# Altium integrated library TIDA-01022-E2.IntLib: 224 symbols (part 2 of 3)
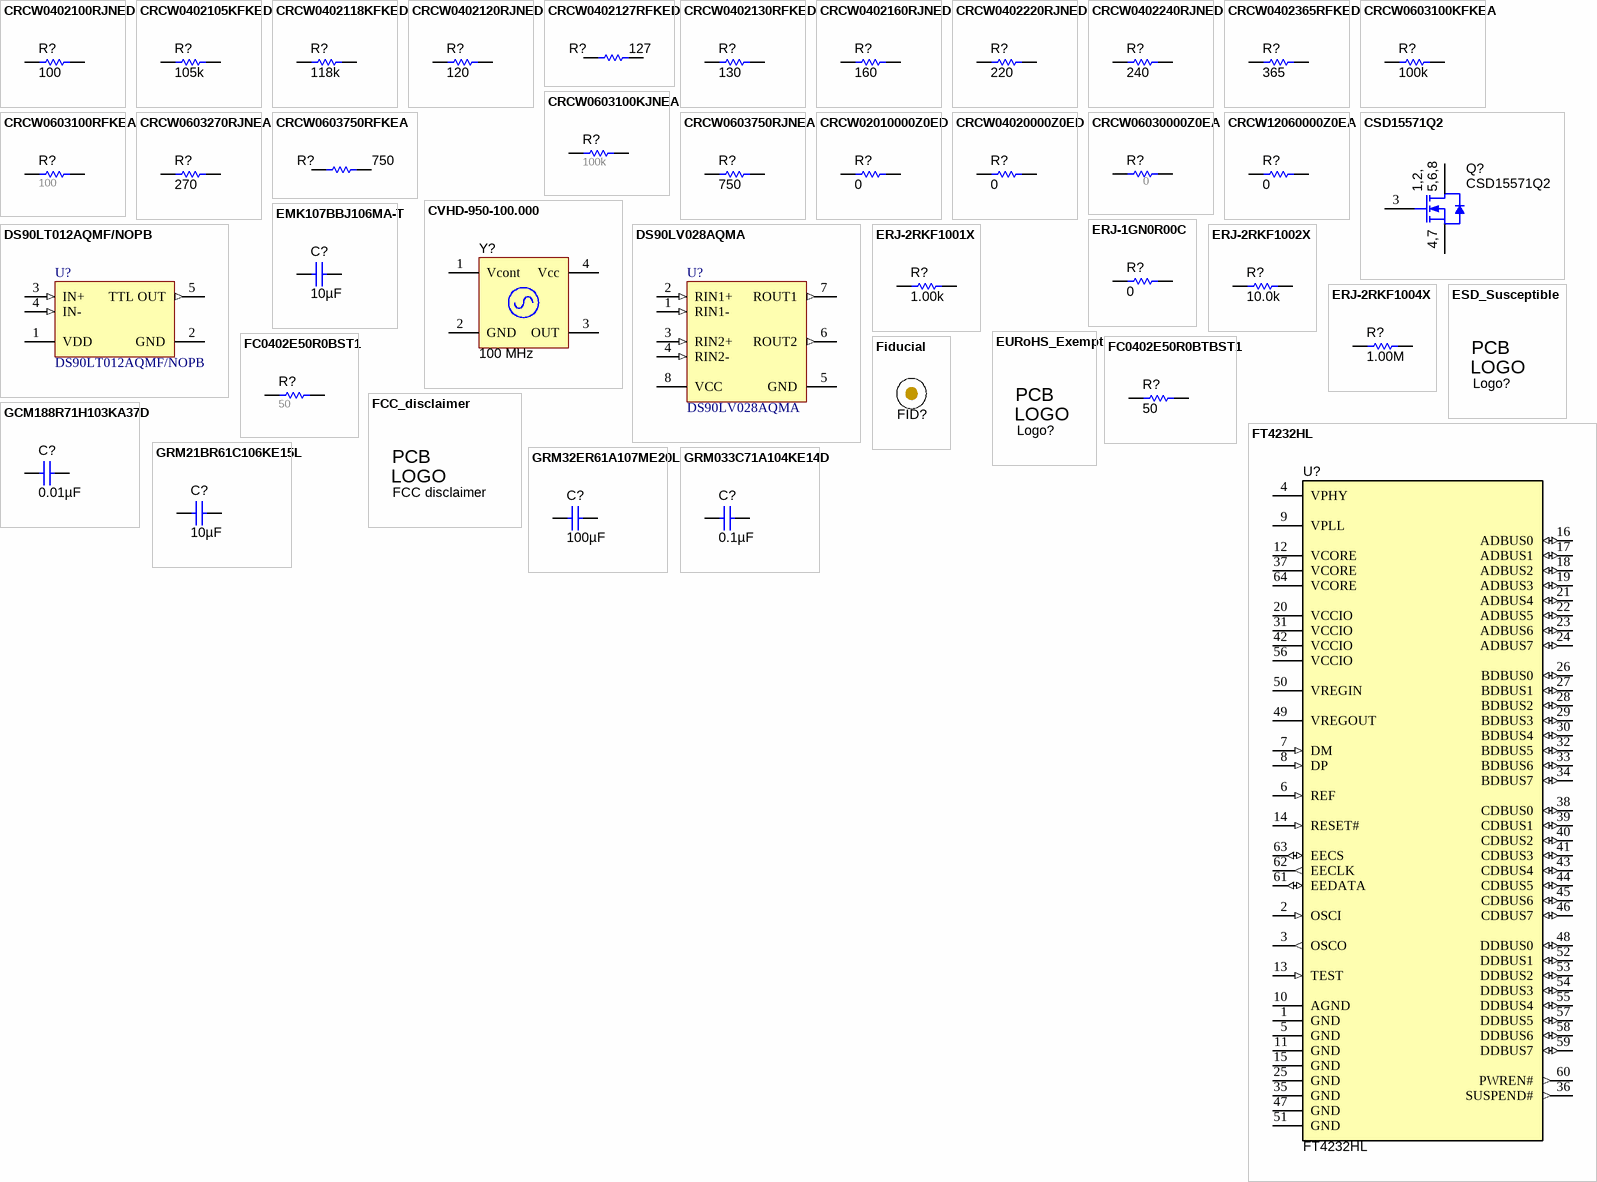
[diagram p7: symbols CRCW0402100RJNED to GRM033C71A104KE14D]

## CRCW0402105KFKED
designator R?  ValueDisplayed: 105k  (hidden comment: CRCW0402105KFKED)
RES, 105 k, 1%, 0.063 W, 0402; Manufacturer: Vishay-Dale; CompType: Resistor; Value: 105k; Res_ohm: 105000; Tolerance_%: 1; Power_W: 0.063; Value2: 0.063W; VDC_V: 50; TempCo: 100 ppm/C; SizeArea_mm2: 0.5; SizeZ_mm: 0.6; EIA_Code: E96; U/M: EA; AEC Category: Q200
signal-integrity model Resistor
simulation model Resistor
footprint 0402
footprint 0402M
footprint 0402L
footprint 0402S
pins: 1, 2

## CRCW0402118KFKED
designator R?  ValueDisplayed: 118k  (hidden comment: CRCW0402118KFKED)
RES, 118 k, 1%, 0.063 W, 0402; Manufacturer: Vishay-Dale; CompType: Resistor; Value: 118k; Res_ohm: 118000; Tolerance_%: 1; Power_W: 0.063; Value2: 0.063W; VDC_V: 50; TempCo: 100 ppm/C; SizeArea_mm2: 0.5; SizeZ_mm: 0.6; EIA_Code: E96; U/M: EA; AEC Category: Q200
signal-integrity model Resistor
simulation model Resistor
footprint 0402
footprint 0402M
footprint 0402L
footprint 0402S
pins: 1, 2

## CRCW0402120RJNED
designator R?  ValueDisplayed: 120  (hidden comment: CRCW0402120RJNED)
RES, 120, 5%, 0.063 W, 0402; Manufacturer: Vishay-Dale; CompType: Resistor; Value: 120; Value_Code: 120R; Tolerance_%: 5; Power_W: 0.063; Value2: 0.063W; VDC_V: 50; TempCo: 200 ppm/C; SizeArea_mm2: 0.5; SizeX_mm: 1; SizeZ_mm: 0.6; EIA_Code: E24; U/M: EA; AEC Category: Q200
signal-integrity model Resistor
simulation model Resistor
footprint 0402
footprint 0402M
footprint 0402L
footprint 0402S
pins: 1, 2

## CRCW0402127RFKED
designator R?  ValueDisplayed: 127  (hidden comment: CRCW0402127RFKED)
RES, 127, 1%, 0.063 W, 0402; Manufacturer: Vishay-Dale; CompType: Resistor; Value: 127; Value_Code: 127R; Tolerance_%: 1; Power_W: 0.063; Value2: 0.063W; VDC_V: 50; TempCo: 100 ppm/C; SizeArea_mm2: 0.5; SizeZ_mm: 0.6; EIA_Code: E96; U/M: EA; AEC Category: Q200
signal-integrity model Resistor
simulation model Resistor
footprint 0402
footprint 0402M
footprint 0402L
footprint 0402S
pins: 1, 2

## CRCW0402130RFKED
designator R?  ValueDisplayed: 130  (hidden comment: CRCW0402130RFKED)
RES, 130, 1%, 0.063 W, 0402; Manufacturer: Vishay-Dale; CompType: Resistor; Value: 130; Value_Code: 130R; Tolerance_%: 1; Power_W: 0.063; Value2: 0.063W; VDC_V: 50; TempCo: 100 ppm/C; SizeArea_mm2: 0.5; SizeZ_mm: 0.6; EIA_Code: E96; U/M: EA; AEC Category: Q200
signal-integrity model Resistor
simulation model Resistor
footprint 0402
footprint 0402M
footprint 0402L
footprint 0402S
pins: 1, 2

## CRCW0402160RJNED
designator R?  ValueDisplayed: 160  (hidden comment: CRCW0402160RJNED)
RES, 160, 5%, 0.063 W, 0402; Manufacturer: Vishay-Dale; CompType: Resistor; Value: 160; Value_Code: 160R; Tolerance_%: 5; Power_W: 0.063; Value2: 0.063W; VDC_V: 50; TempCo: 200 ppm/C; SizeArea_mm2: 0.5; SizeX_mm: 1; SizeZ_mm: 0.6; EIA_Code: E24; U/M: EA; AEC Category: Q200
signal-integrity model Resistor
simulation model Resistor
footprint 0402
footprint 0402M
footprint 0402L
footprint 0402S
pins: 1, 2

## CRCW0402220RJNED
designator R?  ValueDisplayed: 220  (hidden comment: CRCW0402220RJNED)
RES, 220, 5%, 0.063 W, 0402; Manufacturer: Vishay-Dale; CompType: Resistor; Value: 220; Value_Code: 220R; Tolerance_%: 5; Power_W: 0.063; Value2: 0.063W; VDC_V: 50; TempCo: 200 ppm/C; SizeArea_mm2: 0.5; SizeX_mm: 1; SizeZ_mm: 0.6; EIA_Code: E24; U/M: EA; AEC Category: Q200
signal-integrity model Resistor
simulation model Resistor
footprint 0402
footprint 0402M
footprint 0402L
footprint 0402S
pins: 1, 2

## CRCW0402240RJNED
designator R?  ValueDisplayed: 240  (hidden comment: CRCW0402240RJNED)
RES, 240, 5%, 0.063 W, 0402; Manufacturer: Vishay-Dale; CompType: Resistor; Value: 240; Value_Code: 240R; Tolerance_%: 5; Power_W: 0.063; Value2: 0.063W; VDC_V: 50; TempCo: 200 ppm/C; SizeArea_mm2: 0.5; SizeX_mm: 1; SizeZ_mm: 0.6; EIA_Code: E24; U/M: EA; AEC Category: Q200
signal-integrity model Resistor
simulation model Resistor
footprint 0402
footprint 0402M
footprint 0402L
footprint 0402S
pins: 1, 2

## CRCW0402365RFKED
designator R?  ValueDisplayed: 365  (hidden comment: CRCW0402365RFKED)
RES, 365, 1%, 0.063 W, 0402; Manufacturer: Vishay-Dale; CompType: Resistor; Value: 365; Value_Code: 365R; Tolerance_%: 1; Power_W: 0.063; Value2: 0.063W; VDC_V: 50; TempCo: 100 ppm/C; SizeArea_mm2: 0.5; SizeZ_mm: 0.6; EIA_Code: E96; U/M: EA; AEC Category: Q200
signal-integrity model Resistor
simulation model Resistor
footprint 0402
footprint 0402M
footprint 0402L
footprint 0402S
pins: 1, 2

## CRCW0603100KFKEA
designator R?  ValueDisplayed: 100k  (hidden comment: CRCW0603100KFKEA)
RES, 100 k, 1%, 0.1 W, 0603; Manufacturer: Vishay-Dale; CompType: Resistor; Value: 100k; Res_ohm: 100000; Tolerance_%: 1; Power_W: 0.1; Value2: 0.1W; VDC_V: 75; TempCo: 100 ppm/C; SizeArea_mm2: 1.28; SizeX_mm: 1.6; SizeY_mm: 0.8; EIA_Code: E96; U/M: EA; AEC Category: Q200
signal-integrity model Resistor
simulation model Resistor
footprint 0603
footprint 0603M
footprint 0603L
footprint 0603_HV
footprint 0603S
pins: 1, 2

## CRCW0603100KJNEA
designator R?  ValueDisplayed: 100k  (hidden comment: CRCW0603100KJNEA)
RES, 100 k, 5%, 0.1 W, 0603; Manufacturer: Vishay-Dale; CompType: Resistor; Tolerance_%: 5; VDC_V: 75; Power_W: 0.1; Res_ohm: 100000; Value: 100k; U/M: EA; Value2: 0.1W; EIA_Code: E24; TempCo: 200 ppm/C; SizeArea_mm2: 1.28; SizeX_mm: 1.6; SizeY_mm: 0.8; SizeZ_mm: 1; AEC Category: Q200
signal-integrity model Resistor
simulation model Resistor
footprint 0603
footprint 0603M
footprint 0603L
footprint 0603_HV
footprint 0603S
pins: 1, 2

## CRCW0603100RFKEA
designator R?  ValueDisplayed: 100  (hidden comment: CRCW0603100RFKEA)
RES, 100, 1%, 0.1 W, 0603; Manufacturer: Vishay-Dale; CompType: Resistor; Tolerance_%: 1; VDC_V: 75; Power_W: 0.1; Value: 100; U/M: EA; Value_Code: 100R; Value2: 0.1W; EIA_Code: E96; TempCo: 100 ppm/C; SizeArea_mm2: 1.28; SizeX_mm: 1.6; SizeY_mm: 0.8; AEC Category: Q200
signal-integrity model Resistor
simulation model Resistor
footprint 0603
footprint 0603M
footprint 0603L
footprint 0603_HV
footprint 0603S
pins: 1, 2

## CRCW0603270RJNEA
designator R?  ValueDisplayed: 270  (hidden comment: CRCW0603270RJNEA)
RES, 270, 5%, 0.1 W, 0603; Manufacturer: Vishay-Dale; CompType: Resistor; Value: 270; Value_Code: 270R; Tolerance_%: 5; Power_W: 0.1; Value2: 0.1W; VDC_V: 75; TempCo: 200 ppm/C; SizeArea_mm2: 1.28; SizeX_mm: 1.6; SizeY_mm: 0.8; SizeZ_mm: 1; EIA_Code: E24; U/M: EA; AEC Category: Q200
signal-integrity model Resistor
simulation model Resistor
footprint 0603
footprint 0603M
footprint 0603L
footprint 0603_HV
footprint 0603S
pins: 1, 2

## CRCW0603750RFKEA
designator R?  ValueDisplayed: 750  (hidden comment: CRCW0603750RFKEA)
RES, 750, 1%, 0.1 W, 0603; Manufacturer: Vishay-Dale; CompType: Resistor; Value: 750; Value_Code: 750R; Tolerance_%: 1; Power_W: 0.1; Value2: 0.1W; VDC_V: 75; TempCo: 100 ppm/C; SizeArea_mm2: 1.28; SizeX_mm: 1.6; SizeY_mm: 0.8; EIA_Code: E96; U/M: EA; AEC Category: Q200
signal-integrity model Resistor
simulation model Resistor
footprint 0603
footprint 0603M
footprint 0603L
footprint 0603_HV
footprint 0603S
pins: 1, 2

## CRCW0603750RJNEA
designator R?  ValueDisplayed: 750  (hidden comment: CRCW0603750RJNEA)
RES, 750, 5%, 0.1 W, 0603; Manufacturer: Vishay-Dale; CompType: Resistor; Value: 750; Value_Code: 750R; Tolerance_%: 5; Power_W: 0.1; Value2: 0.1W; VDC_V: 75; TempCo: 200 ppm/C; SizeArea_mm2: 1.28; SizeX_mm: 1.6; SizeY_mm: 0.8; SizeZ_mm: 1; EIA_Code: E24; U/M: EA; AEC Category: Q200
signal-integrity model Resistor
simulation model Resistor
footprint 0603
footprint 0603M
footprint 0603L
footprint 0603_HV
footprint 0603S
pins: 1, 2

## CRCW02010000Z0ED
designator R?  ValueDisplayed: 0  (hidden comment: CRCW02010000Z0ED)
RES, 0, 5%, 0.05 W, 0201; Manufacturer: Vishay-Dale; CompType: Resistor; Value: 0; Value_Code: 0000; Tolerance_%: 5; Power_W: 0.05; Value2: 0.05W; TempCo: ppm/C; SizeArea_mm2: 0.18; SizeX_mm: 0.6; SizeY_mm: 0.3; SizeZ_mm: 0.26; EIA_Code: E24; U/M: EA; AEC Category: Q200; AEC Qualified: N
signal-integrity model Resistor
simulation model Resistor
footprint 0201_adc (Data from Kemet datasheet CC101_COM dated 7/28/11)
footprint 0201M
footprint 0201L
footprint 0201_Silk
pins: 1, 2

## CRCW04020000Z0ED
designator R?  ValueDisplayed: 0  (hidden comment: CRCW04020000Z0ED)
RES, 0, 5%, 0.063 W, 0402; Manufacturer: Vishay-Dale; CompType: Resistor; Value: 0; Value_Code: 0000; Tolerance_%: 5; Power_W: 0.063; Value2: 0.063W; VDC_V: 50; TempCo: 200 ppm/C; SizeArea_mm2: 0.5; SizeX_mm: 1; SizeZ_mm: 0.6; EIA_Code: E24; U/M: EA; AEC Category: Q200
signal-integrity model Resistor
simulation model Resistor
footprint 0402
footprint 0402M
footprint 0402L
footprint 0402S
pins: 1, 2

## CRCW06030000Z0EA
designator R?  ValueDisplayed: 0  (hidden comment: CRCW06030000Z0EA)
RES, 0, 5%, 0.1 W, 0603; Manufacturer: Vishay-Dale; CompType: Resistor; Tolerance_%: 5; VDC_V: 75; Power_W: 0.1; Value: 0; U/M: EA; Value_Code: 0000; Value2: 0.1W; EIA_Code: E24; TempCo: 200 ppm/C; SizeArea_mm2: 1.28; SizeX_mm: 1.6; SizeY_mm: 0.8; SizeZ_mm: 1; AEC Category: Q200
signal-integrity model Resistor
simulation model Resistor
footprint 0603
footprint 0603M
footprint 0603L
footprint 0603_HV
footprint 0603S
pins: 1, 2

## CRCW12060000Z0EA
designator R?  ValueDisplayed: 0  (hidden comment: CRCW12060000Z0EA)
RES, 0, 5%, 0.25 W, 1206; Manufacturer: Vishay-Dale; CompType: Resistor; Value: 0; Value_Code: 0000; Tolerance_%: 5; Power_W: 0.25; Value2: 0.25W; VDC_V: 200; TempCo: 200 ppm/C; SizeArea_mm2: 5.12; SizeX_mm: 3.2; SizeY_mm: 1.6; SizeZ_mm: 1.35; EIA_Code: E24; U/M: EA; AEC Category: Q200
signal-integrity model Resistor
simulation model Resistor
footprint 1206
footprint 1206M
footprint 1206L
pins: 1, 2

## CSD15571Q2
designator Q?
MOSFET, N-CH, 20 V, 10 A, DQK0006C (WSON-6); Manufacturer: Texas Instruments; Alternate Manufacturer: None; U/M: EA; ChType: N; Value: 20V; VdsMax_V: 20; Value1: 19.2 ohm; Rdson45_ohm: 19.2; Value2: 2.5 nC; QgTyp_nC: 2.5; IdsMax_A: 10; SizeAreaWB_mm2: 9; SizeArea_mm2: 4; SizeX_mm: 2; SizeZ_mm: 0.8; AEC Category: Q101
footprint DQK0006C
pins: 1 D, 2 D, 3 G, 4 S, 5 D, 6 D, 7 S, 8 D

## CVHD-950-100.000
designator Y?  Frequency: 100 MHz  (hidden comment: CVHD-950-100.000)
VCXO, 100 MHz, 3.3V, SMD; Manufacturer: Crystek Corporation; SymbolCreator: a0412235; CompType: Oscillator; U/M: EA; TaMin_C: 0; TaMax_C: 70; Frequency Stability: ±20ppm
footprint OSC_CVHD-950-4
footprint OSC_CVHD-950-4_ExtPads
pins: 1 Vcont, 2 GND (power), 3 OUT, 4 Vcc (power)

## DS90LT012AQMF/NOPB
designator U?
Automotive LVDS Differential Line Receiver, 5-pin SOT-23, Pb-Free; Manufacturer: Texas Instruments; PackageTopMarking: N03Q*XTT; PowerWise: N; CompType: Interface IC
footprint MF05A_N (SOT23, 5-Leads, Body 2.9x1.6mm, Pitch 0.95mm, Lead Span 2.8mm, IPC Medium Density)
footprint MF05A_L (SOT23, 5-Leads, Body 2.9x1.6mm, Pitch 0.95mm, Lead Span 2.8mm, IPC High Density)
footprint MF05A_M (SOT23, 5-Leads, Body 2.9x1.6mm, Pitch 0.95mm, Lead Span 2.8mm, IPC Low Density)
pins: 1 VDD (power), 2 GND (power), 3 IN+ (in), 4 IN- (in), 5 TTL OUT (out)

## DS90LV028AQMA
designator U?
Automotive LVDS Dual Differential Line Receiver, 8-pin Narrow SOIC; Manufacturer: Texas Instruments; PackageTopMarking: NSZXTT*90LV0*28AQM; PowerWise: N; CompType: Interface IC
footprint M08A_N (SOIC, 8-Leads, Body 4.9x3.9mm, Pitch 1.27mm, IPC Medium Density)
footprint M08A_L (SOIC, 8-Leads, Body 4.9x3.9mm, Pitch 1.27mm, IPC High Density)
footprint M08A_M (SOIC, 8-Leads, Body 4.9x3.9mm, Pitch 1.27mm, IPC Low Density)
pins: 1 RIN1- (in), 2 RIN1+ (in), 3 RIN2+ (in), 4 RIN2- (in), 5 GND (power), 6 ROUT2 (out), 7 ROUT1 (out), 8 VCC (power)

## EMK107BBJ106MA-T
designator C?  ValueDisplayed: 10µF  (hidden comment: EMK107BBJ106MA-T)
CAP, CERM, 10 µF, 16 V, +/- 20%, X5R, 0603; Manufacturer: Taiyo Yuden; Polarized: N; CompType: Capacitor; Value: 10uF; U/M: EA; Cap_F: 0.00001; Tolerance_%: 20; Value1: Unknown; VDC_V: 16; Value2: 16V; TaMin_C: -55; TaMax_C: 85; Cap_Case: 0603; SizeArea_mm2: 1.28; SizeAreaWB_mm2: 4.68; SizeX_mm: 1.6; SizeY_mm: 0.8; SizeZ_mm: 1; AEC Category: Q200
signal-integrity model Cap
simulation model Cap
footprint 0603
footprint 0603M
footprint 0603L
footprint 0603_HV
footprint 0603S
pins: 1, 2

## ERJ-1GN0R00C
designator R?  ValueDisplayed: 0  (hidden comment: ERJ-1GN0R00C)
RES, 0, 5%, 0.05 W, AEC-Q200 Grade 0, 0201; Manufacturer: Panasonic; CompType: Resistor; Tolerance_%: 5; Power_W: 0.05; Value: 0; U/M: EA; Value_Code: 0000; Value2: 0.05W; EIA_Code: E24; TempCo: ppm/C; SizeArea_mm2: 0.18; SizeX_mm: 0.6; SizeY_mm: 0.3; SizeZ_mm: 0.26; AEC Category: Q200; AEC Qualified: Y
signal-integrity model Resistor
simulation model Resistor
footprint 0201
footprint 0201M
footprint 0201L
footprint 0201_Silk
pins: 1, 2

## ERJ-2RKF1001X
designator R?  ValueDisplayed: 1.00k  (hidden comment: ERJ-2RKF1001X)
RES, 1.00 k, 1%, 0.1 W, 0402; Manufacturer: Panasonic; CompType: Resistor; Value: 1.00k; Res_ohm: 1000; Value_Code: 1k00; Tolerance_%: 1; Power_W: 0.1; Value2: 0.1W; VDC_V: 50; TempCo: 100 ppm/C; SizeArea_mm2: 0.5; SizeZ_mm: 0.6; EIA_Code: E96; U/M: EA; AEC Category: Q200
signal-integrity model Resistor
simulation model Resistor
footprint 0402
footprint 0402M
footprint 0402L
footprint 0402S
pins: 1, 2

## ERJ-2RKF1002X
designator R?  ValueDisplayed: 10.0k  (hidden comment: ERJ-2RKF1002X)
RES, 10.0 k, 1%, 0.1 W, 0402; Manufacturer: Panasonic; CompType: Resistor; Value: 10.0k; Res_ohm: 10000; Value_Code: 10k0; Tolerance_%: 1; Power_W: 0.1; Value2: 0.1W; VDC_V: 50; TempCo: 100 ppm/C; SizeArea_mm2: 0.5; SizeZ_mm: 0.6; EIA_Code: E96; U/M: EA; AEC Category: Q200
signal-integrity model Resistor
simulation model Resistor
footprint 0402
footprint 0402M
footprint 0402L
footprint 0402S
pins: 1, 2

## ERJ-2RKF1004X
designator R?  ValueDisplayed: 1.00M  (hidden comment: ERJ-2RKF1004X)
RES, 1.00 M, 1%, 0.1 W, 0402; Manufacturer: Panasonic; CompType: Resistor; Value: 1.00Meg; Res_ohm: 1000000; Value_Code: 1M00; Tolerance_%: 1; Power_W: 0.1; Value2: 0.1W; VDC_V: 50; TempCo: 100 ppm/C; SizeArea_mm2: 0.5; SizeZ_mm: 0.6; EIA_Code: E96; U/M: EA; AEC Category: Q200
signal-integrity model Resistor
simulation model Resistor
footprint 0402
footprint 0402M
footprint 0402L
footprint 0402S
pins: 1, 2

## ESD_Susceptible
designator Logo?, comment ESD Susceptible  (value not drawn)  (no BOM)
ESD Susceptible Symbol; SymbolCreator: a0412235
footprint ESD_Overlay_Large
footprint ESD_Overlay_Medium
footprint ESD_Overlay_Small

## EURoHS_Exempt
designator Logo?, comment EU RoHS Exempt Logo  (value not drawn)  (no BOM)
SymbolCreator: a0412235
footprint EURoHS_Exempt_60mil
footprint EURoHS_Exempt_60mil_Stacked

## FC0402E50R0BST1
designator R?  ValueDisplayed: 50  (hidden comment: FC0402E50R0BST1)
RES, 50, 0.1%, 0.05 W, 0402; Manufacturer: Vishay-Dale; CompType: Resistor; Value: 50; Value_Code: 50R0; Tolerance_%: 0.1; Power_W: 0.05; Value2: 0.05W; TempCo: 25 ppm/C; U/M: EA; SizeArea_mm2: 0.5; SizeX_mm: 1; SizeZ_mm: 0.6; AEC Category: Q200; AEC Qualified: N
signal-integrity model Resistor
simulation model Resistor
footprint 0402
footprint 0402M
footprint 0402L
footprint 0402S
pins: 1, 2

## FC0402E50R0BTBST1
designator R?  ValueDisplayed: 50  (hidden comment: FC0402E50R0BTBST1)
RES, 50, 0.1%, 0.5 W, 0402; Manufacturer: Vishay Thin Film; CompType: Resistor; Value: 50; Value_Code: 50R0; Tolerance_%: 0.1; Power_W: 0.5; Value2: 0.5W; TempCo: 0.1 ppm/C; SizeX_mm: 1; SizeZ_mm: 0.6; U/M: EA; AEC Category: Q200; AEC Qualified: N
signal-integrity model Resistor
simulation model Resistor
footprint 0402
footprint 0402M
footprint 0402L
footprint 0402S
pins: 1, 2

## FCC_disclaimer
designator Logo?, comment FCC disclaimer  (no BOM)
FCC_disclaimer; SymbolCreator: codlsc
footprint FCC_disclaimer
footprint FCC_disclaimer_stacked

## Fiducial
designator FID?  (value not drawn)
Fiducial mark.  There is nothing to buy or mount.; SymbolCreator: codlsc
footprint Fiducial10-30
footprint Fiducial10-20
footprint Fiducial15-30
footprint Fiducial20-40
footprint Fiducial6.4-20

## FT4232HL
designator U?
Quad High Speed USB to Multipurpose UART/MPSSE IC; Manufacturer: FTDI; SymbolCreator: a0411947
footprint LQFP64_N
footprint LQFP64_M
footprint LQFP64_L
pins: 1 GND (power), 2 OSCI (in), 3 OSCO (out), 4 VPHY (power), 5 GND (power), 6 REF (in), 7 DM (in), 8 DP (in), 9 VPLL (power), 10 AGND (power), 11 GND (power), 12 VCORE (power), 13 TEST (in), 14 RESET# (in), 15 GND (power), 16 ADBUS0 (io), 17 ADBUS1 (io), 18 ADBUS2 (io), 19 ADBUS3 (io), 20 VCCIO (power), 21 ADBUS4 (io), 22 ADBUS5 (io), 23 ADBUS6 (io), 24 ADBUS7 (io), 25 GND (power), 26 BDBUS0 (io), 27 BDBUS1 (io), 28 BDBUS2 (io), 29 BDBUS3 (io), 30 BDBUS4 (io), 31 VCCIO (power), 32 BDBUS5 (io), 33 BDBUS6 (io), 34 BDBUS7 (io), 35 GND (power), 36 SUSPEND# (out), 37 VCORE (power), 38 CDBUS0 (io), 39 CDBUS1 (io), 40 CDBUS2 (io), 41 CDBUS3 (io), 42 VCCIO (power), 43 CDBUS4 (io), 44 CDBUS5 (io), 45 CDBUS6 (io), 46 CDBUS7 (io), 47 GND (power), 48 DDBUS0 (io), 49 VREGOUT (power), 50 VREGIN (power), 51 GND (power), 52 DDBUS1 (io), 53 DDBUS2 (io), 54 DDBUS3 (io), 55 DDBUS4 (io), 56 VCCIO (power), 57 DDBUS5 (io), 58 DDBUS6 (io), 59 DDBUS7 (io), 60 PWREN# (out), 61 EEDATA (io), 62 EECLK (out), 63 EECS (io), 64 VCORE (power)

## GCM188R71H103KA37D
designator C?  ValueDisplayed: 0.01µF  (hidden comment: GCM188R71H103KA37D)
CAP, CERM, 0.01 µF, 50 V, +/- 10%, X7R, AEC-Q200 Grade 1, 0603; Manufacturer: MuRata; Polarized: N; CompType: Capacitor; Value: 0.01uF; U/M: EA; Cap_F: 0.00000001; Tolerance_%: 10; Value1: Unknown; VDC_V: 50; Value2: 50V; TaMin_C: -55; TaMax_C: 125; Cap_Case: 0603; SizeArea_mm2: 1.28; SizeAreaWB_mm2: 4.68; SizeX_mm: 1.6; SizeY_mm: 0.8; SizeZ_mm: 1; AEC Category: Q200; AEC Qualified: Y
signal-integrity model Cap
simulation model Cap
footprint 0603
footprint 0603M
footprint 0603L
footprint 0603_HV
footprint 0603S
pins: 1, 2

## GRM21BR61C106KE15L
designator C?  ValueDisplayed: 10µF  (hidden comment: GRM21BR61C106KE15L)
CAP, CERM, 10 µF, 16 V, +/- 10%, X5R, 0805; Manufacturer: MuRata; Polarized: N; CompType: Capacitor; Value: 10uF; U/M: EA; Cap_F: 0.00001; Tolerance_%: 10; ESR_ohm: 0.008; Value1: 0.008 ohm; VDC_V: 16; Value2: 16V; TaMin_C: -55; TaMax_C: 85; Cap_Case: 0805; SizeArea_mm2: 2.5; SizeAreaWB_mm2: 6.75; SizeX_mm: 2; SizeY_mm: 1.25; SizeZ_mm: 1.45; AEC Category: Q200
signal-integrity model Cap
simulation model Cap
footprint 0805_HV
footprint 0805_HV1
footprint 0805
footprint 0805M
footprint 0805L
pins: 1, 2

## GRM32ER61A107ME20L
designator C?  ValueDisplayed: 100µF  (hidden comment: GRM32ER61A107ME20L)
CAP, CERM, 100 µF, 10 V, +/- 20%, X5R, 1210; Manufacturer: MuRata; Polarized: N; CompType: Capacitor; Value: 100uF; U/M: EA; Cap_F: 0.0001; Tolerance_%: 20; Value1: Unknown; VDC_V: 10; Value2: 10V; TaMin_C: -55; TaMax_C: 85; Cap_Case: 1210; SizeArea_mm2: 8; SizeAreaWB_mm2: 14.7; SizeX_mm: 3.2; SizeY_mm: 2.5; SizeZ_mm: 2.7; AEC Category: Q200
signal-integrity model Cap
simulation model Cap
footprint 1210_270
footprint 1210_270M
footprint 1210_270L
pins: 1, 2

## GRM033C71A104KE14D
designator C?  ValueDisplayed: 0.1µF  (hidden comment: GRM033C71A104KE14D)
CAP, CERM, 0.1 µF, 10 V, +/- 10%, X7S, 0201; Manufacturer: MuRata; Cap_Case: 0201; Polarized: N; TaMax_C: 125; TaMin_C: -55; Tolerance_%: 10; Cap_F: 0.0000001; CompType: Capacitor; Value: 0.1uF; Value1: Unknown; Value2: 10V; U/M: EA; SizeArea_mm2: 0.18; SizeAreaWB_mm2: 2.08; SizeX_mm: 0.6; SizeY_mm: 0.3; SizeZ_mm: 0.26; AEC Category: Q200
signal-integrity model Cap
simulation model Cap
footprint 0201_adc (Data from Kemet datasheet CC101_COM dated 7/28/11)
footprint 0201M
footprint 0201L
footprint 0201_Silk
pins: 1, 2

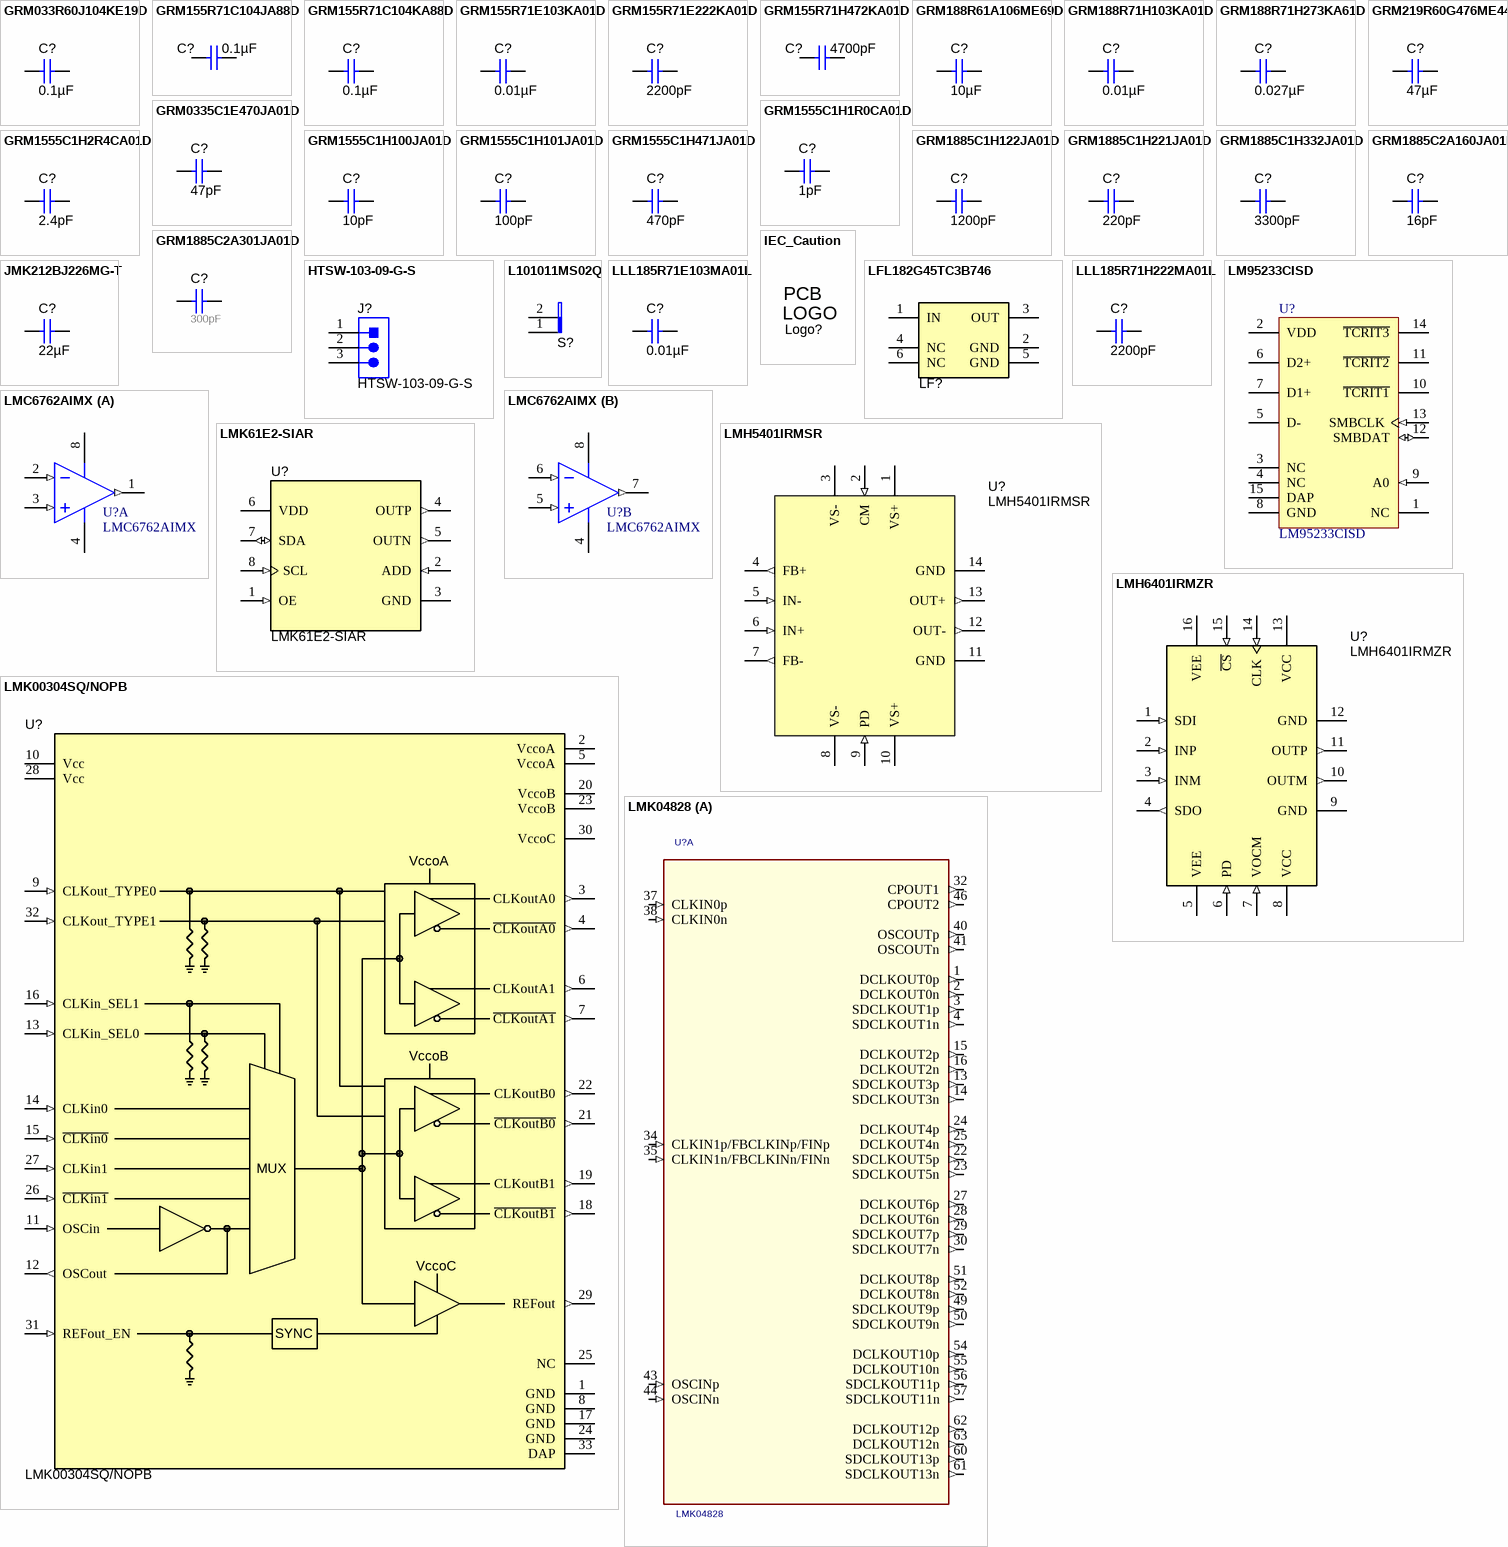
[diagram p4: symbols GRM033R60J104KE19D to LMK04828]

## GRM033R60J104KE19D
designator C?  ValueDisplayed: 0.1µF  (hidden comment: GRM033R60J104KE19D)
CAP, CERM, 0.1 µF, 6.3 V, +/- 10%, X5R, 0201; Manufacturer: MuRata; Polarized: N; CompType: Capacitor; Value: 0.1uF; U/M: EA; Cap_F: 0.0000001; Tolerance_%: 10; Value1: Unknown; VDC_V: 6.3; Value2: 6.3V; TaMin_C: -55; TaMax_C: 85; Cap_Case: 0201; SizeArea_mm2: 0.18; SizeAreaWB_mm2: 2.08; SizeX_mm: 0.6; SizeY_mm: 0.3; SizeZ_mm: 0.33; AEC Category: Q200
signal-integrity model Cap
simulation model Cap
footprint 0201_033
footprint 0201_033M
footprint 0201_033L
pins: 1, 2

## GRM155R71C104JA88D
designator C?  ValueDisplayed: 0.1µF  (hidden comment: GRM155R71C104JA88D)
CAP, CERM, 0.1 µF, 16 V, +/- 5%, X7R, 0402; Manufacturer: MuRata; Polarized: N; CompType: Capacitor; Value: 0.1uF; U/M: EA; Cap_F: 0.0000001; Tolerance_%: 5; Value1: Unknown; VDC_V: 16; Value2: 16V; TaMin_C: -55; TaMax_C: 125; Cap_Case: 0402; SizeArea_mm2: 0.5; SizeAreaWB_mm2: 3; SizeX_mm: 1; SizeZ_mm: 0.6; AEC Category: Q200
signal-integrity model Cap
simulation model Cap
footprint 0402
footprint 0402M
footprint 0402L
footprint 0402S
pins: 1, 2

## GRM155R71C104KA88D
designator C?  ValueDisplayed: 0.1µF  (hidden comment: GRM155R71C104KA88D)
CAP, CERM, 0.1 µF, 16 V, +/- 10%, X7R, 0402; Manufacturer: MuRata; Polarized: N; CompType: Capacitor; Value: 0.1uF; U/M: EA; Cap_F: 0.0000001; Tolerance_%: 10; Value1: Unknown; VDC_V: 16; Value2: 16V; TaMin_C: -55; TaMax_C: 125; Cap_Case: 0402; SizeArea_mm2: 0.5; SizeAreaWB_mm2: 3; SizeX_mm: 1; SizeZ_mm: 0.6; AEC Category: Q200
signal-integrity model Cap
simulation model Cap
footprint 0402
footprint 0402M
footprint 0402L
footprint 0402S
pins: 1, 2

## GRM155R71E103KA01D
designator C?  ValueDisplayed: 0.01µF  (hidden comment: GRM155R71E103KA01D)
CAP, CERM, 0.01 µF, 25 V, +/- 10%, X7R, 0402; Manufacturer: MuRata; Polarized: N; CompType: Capacitor; Value: 0.01uF; U/M: EA; Cap_F: 0.00000001; Tolerance_%: 10; Value1: Unknown; VDC_V: 25; Value2: 25V; TaMin_C: -55; TaMax_C: 125; Cap_Case: 0402; SizeArea_mm2: 0.5; SizeAreaWB_mm2: 3; SizeX_mm: 1; SizeZ_mm: 0.6; AEC Category: Q200
signal-integrity model Cap
simulation model Cap
footprint 0402
footprint 0402M
footprint 0402L
footprint 0402S
pins: 1, 2

## GRM155R71E222KA01D
designator C?  ValueDisplayed: 2200pF  (hidden comment: GRM155R71E222KA01D)
CAP, CERM, 2200 pF, 25 V, +/- 10%, X7R, 0402; Manufacturer: MuRata; Polarized: N; CompType: Capacitor; Value: 2200pF; U/M: EA; Cap_F: 0.0000000022; Tolerance_%: 10; Value1: Unknown; VDC_V: 25; Value2: 25V; TaMin_C: -55; TaMax_C: 125; Cap_Case: 0402; SizeArea_mm2: 0.5; SizeAreaWB_mm2: 3; SizeX_mm: 1; SizeZ_mm: 0.6; AEC Category: Q200
signal-integrity model Cap
simulation model Cap
footprint 0402
footprint 0402M
footprint 0402L
footprint 0402S
pins: 1, 2

## GRM155R71H472KA01D
designator C?  ValueDisplayed: 4700pF  (hidden comment: GRM155R71H472KA01D)
CAP, CERM, 4700 pF, 50 V, +/- 10%, X7R, 0402; Manufacturer: MuRata; Polarized: N; CompType: Capacitor; Value: 4700pF; U/M: EA; Cap_F: 0.0000000047; Tolerance_%: 10; Value1: Unknown; VDC_V: 50; Value2: 50V; TaMin_C: -55; TaMax_C: 125; Cap_Case: 0402; SizeArea_mm2: 0.5; SizeAreaWB_mm2: 3; SizeX_mm: 1; SizeZ_mm: 0.6; AEC Category: Q200
signal-integrity model Cap
simulation model Cap
footprint 0402
footprint 0402M
footprint 0402L
footprint 0402S
pins: 1, 2

## GRM188R61A106ME69D
designator C?  ValueDisplayed: 10µF  (hidden comment: GRM188R61A106ME69D)
CAP, CERM, 10 µF, 10 V, +/- 20%, X5R, 0603; Manufacturer: MuRata; Polarized: N; CompType: Capacitor; Value: 10uF; U/M: EA; Cap_F: 0.00001; Tolerance_%: 20; Value1: Unknown; VDC_V: 10; Value2: 10V; TaMin_C: -55; TaMax_C: 85; Cap_Case: 0603; SizeArea_mm2: 1.28; SizeAreaWB_mm2: 4.68; SizeX_mm: 1.6; SizeY_mm: 0.8; SizeZ_mm: 1; AEC Category: Q200
signal-integrity model Cap
simulation model Cap
footprint 0603
footprint 0603M
footprint 0603L
footprint 0603_HV
footprint 0603S
pins: 1, 2

## GRM188R71H103KA01D
designator C?  ValueDisplayed: 0.01µF  (hidden comment: GRM188R71H103KA01D)
CAP, CERM, 0.01 µF, 50 V, +/- 10%, X7R, 0603; Manufacturer: MuRata; Polarized: N; CompType: Capacitor; Value: 0.01uF; U/M: EA; Cap_F: 0.00000001; Tolerance_%: 10; Value1: Unknown; VDC_V: 50; Value2: 50V; TaMin_C: -55; TaMax_C: 125; Cap_Case: 0603; SizeArea_mm2: 1.28; SizeAreaWB_mm2: 4.68; SizeX_mm: 1.6; SizeY_mm: 0.8; SizeZ_mm: 1; AEC Category: Q200
signal-integrity model Cap
simulation model Cap
footprint 0603
footprint 0603M
footprint 0603L
footprint 0603_HV
footprint 0603S
pins: 1, 2

## GRM188R71H273KA61D
designator C?  ValueDisplayed: 0.027µF  (hidden comment: GRM188R71H273KA61D)
CAP, CERM, 0.027 µF, 50 V, +/- 10%, X7R, 0603; Manufacturer: MuRata; Cap_Case: 0603; Polarized: N; TaMax_C: 125; TaMin_C: -55; Tolerance_%: 10; VDC_V: 50; Cap_F: 0.000000027; CompType: Capacitor; Value: 0.027uF; Value1: Unknown; Value2: 50V; U/M: EA; AEC Category: Q200; SizeArea_mm2: 1.28; SizeAreaWB_mm2: 4.68; SizeX_mm: 1.6; SizeY_mm: 0.8; SizeZ_mm: 1
signal-integrity model Cap
simulation model Cap
footprint 0603
footprint 0603M
footprint 0603L
footprint 0603_HV
footprint 0603S
pins: 1, 2

## GRM219R60G476ME44D
designator C?  ValueDisplayed: 47µF  (hidden comment: GRM219R60G476ME44D)
CAP, CERM, 47 µF, 4 V, +/- 20%, X5R, 0805; Manufacturer: MuRata; Polarized: N; CompType: Capacitor; Value: 47uF; U/M: EA; Cap_F: 0.000047; Tolerance_%: 20; Value1: Unknown; VDC_V: 4; Value2: 4V; TaMin_C: -55; TaMax_C: 85; Cap_Case: 0805; SizeArea_mm2: 2.5; SizeAreaWB_mm2: 6.75; SizeX_mm: 2; SizeY_mm: 1.25; SizeZ_mm: 1.45; AEC Category: Q200
signal-integrity model Cap
simulation model Cap
footprint 0805_HV
footprint 0805_HV1
footprint 0805
footprint 0805M
footprint 0805L
pins: 1, 2

## GRM0335C1E470JA01D
designator C?  ValueDisplayed: 47pF  (hidden comment: GRM0335C1E470JA01D)
CAP, CERM, 47 pF, 25 V, +/- 5%, C0G/NP0, 0201; Manufacturer: MuRata; Polarized: N; CompType: Capacitor; Value: 47pF; U/M: EA; Cap_F: 0.000000000047; Tolerance_%: 5; Value1: Unknown; VDC_V: 25; Value2: 25V; TaMin_C: -55; TaMax_C: 125; Cap_Case: 0201; SizeArea_mm2: 0.18; SizeAreaWB_mm2: 2.08; SizeX_mm: 0.6; SizeY_mm: 0.3; SizeZ_mm: 0.33; AEC Category: Q200
signal-integrity model Cap
simulation model Cap
footprint 0201_033
footprint 0201_033M
footprint 0201_033L
pins: 1, 2

## GRM1555C1H1R0CA01D
designator C?  ValueDisplayed: 1pF  (hidden comment: GRM1555C1H1R0CA01D)
CAP, CERM, 1 pF, 50 V, +/- 5%, C0G/NP0, 0402; Manufacturer: MuRata; Polarized: N; CompType: Capacitor; Value: 1pF; U/M: EA; Cap_F: 0.000000000001; Tolerance_%: 5; Value1: Unknown; VDC_V: 50; Value2: 50V; TaMin_C: -55; TaMax_C: 125; Cap_Case: 0402; SizeArea_mm2: 0.5; SizeAreaWB_mm2: 3; SizeX_mm: 1; SizeZ_mm: 0.6; AEC Category: Q200
signal-integrity model Cap
simulation model Cap
footprint 0402
footprint 0402M
footprint 0402L
footprint 0402S
pins: 1, 2

## GRM1555C1H2R4CA01D
designator C?  ValueDisplayed: 2.4pF  (hidden comment: GRM1555C1H2R4CA01D)
CAP, CERM, 2.4 pF, 50 V, +/- 5%, C0G/NP0, 0402; Manufacturer: MuRata; Polarized: N; CompType: Capacitor; Value: 2.4pF; U/M: EA; Cap_F: 0.0000000000024; Tolerance_%: 5; Value1: Unknown; VDC_V: 50; Value2: 50V; TaMin_C: -55; TaMax_C: 125; Cap_Case: 0402; SizeArea_mm2: 0.5; SizeAreaWB_mm2: 3; SizeX_mm: 1; SizeZ_mm: 0.6; AEC Category: Q200
signal-integrity model Cap
simulation model Cap
footprint 0402
footprint 0402M
footprint 0402L
footprint 0402S
pins: 1, 2

## GRM1555C1H100JA01D
designator C?  ValueDisplayed: 10pF  (hidden comment: GRM1555C1H100JA01D)
CAP, CERM, 10 pF, 50 V, +/- 5%, C0G/NP0, 0402; Manufacturer: MuRata; Polarized: N; CompType: Capacitor; Value: 10pF; U/M: EA; Cap_F: 0.00000000001; Tolerance_%: 5; Value1: Unknown; VDC_V: 50; Value2: 50V; TaMin_C: -55; TaMax_C: 125; Cap_Case: 0402; SizeArea_mm2: 0.5; SizeAreaWB_mm2: 3; SizeX_mm: 1; SizeZ_mm: 0.6; AEC Category: Q200
signal-integrity model Cap
simulation model Cap
footprint 0402
footprint 0402M
footprint 0402L
footprint 0402S
pins: 1, 2

## GRM1555C1H101JA01D
designator C?  ValueDisplayed: 100pF  (hidden comment: GRM1555C1H101JA01D)
CAP, CERM, 100 pF, 50 V, +/- 5%, C0G/NP0, 0402; Manufacturer: MuRata; Polarized: N; CompType: Capacitor; Value: 100pF; U/M: EA; Cap_F: 0.0000000001; Tolerance_%: 5; Value1: Unknown; VDC_V: 50; Value2: 50V; TaMin_C: -55; TaMax_C: 125; Cap_Case: 0402; SizeArea_mm2: 0.5; SizeAreaWB_mm2: 3; SizeX_mm: 1; SizeZ_mm: 0.6; AEC Category: Q200
signal-integrity model Cap
simulation model Cap
footprint 0402
footprint 0402M
footprint 0402L
footprint 0402S
pins: 1, 2

## GRM1555C1H471JA01D
designator C?  ValueDisplayed: 470pF  (hidden comment: GRM1555C1H471JA01D)
CAP, CERM, 470 pF, 50 V, +/- 5%, C0G/NP0, 0402; Manufacturer: MuRata; Polarized: N; CompType: Capacitor; Value: 470pF; U/M: EA; Cap_F: 0.00000000047; Tolerance_%: 5; Value1: Unknown; VDC_V: 50; Value2: 50V; TaMin_C: -55; TaMax_C: 125; Cap_Case: 0402; SizeArea_mm2: 0.5; SizeAreaWB_mm2: 3; SizeX_mm: 1; SizeZ_mm: 0.6; AEC Category: Q200
signal-integrity model Cap
simulation model Cap
footprint 0402
footprint 0402M
footprint 0402L
footprint 0402S
pins: 1, 2

## GRM1885C1H122JA01D
designator C?  ValueDisplayed: 1200pF  (hidden comment: GRM1885C1H122JA01D)
CAP, CERM, 1200 pF, 50 V, +/- 5%, C0G/NP0, 0603; Manufacturer: MuRata; Cap_Case: 0603; Polarized: N; TaMax_C: 125; TaMin_C: -55; Tolerance_%: 5; VDC_V: 50; Cap_F: 0.0000000012; CompType: Capacitor; Value: 1200pF; Value1: Unknown; Value2: 50V; U/M: EA; SizeArea_mm2: 1.28; SizeAreaWB_mm2: 4.68; SizeX_mm: 1.6; SizeY_mm: 0.8; SizeZ_mm: 1; AEC Category: Q200
signal-integrity model Cap
simulation model Cap
footprint 0603
footprint 0603M
footprint 0603L
footprint 0603_HV
footprint 0603S
pins: 1, 2

## GRM1885C1H221JA01D
designator C?  ValueDisplayed: 220pF  (hidden comment: GRM1885C1H221JA01D)
CAP, CERM, 220 pF, 50 V, +/- 5%, C0G/NP0, 0603; Manufacturer: MuRata; Cap_Case: 0603; Polarized: N; TaMax_C: 125; TaMin_C: -55; Tolerance_%: 5; VDC_V: 50; Cap_F: 0.00000000022; CompType: Capacitor; Value: 220pF; Value1: Unknown; Value2: 50V; U/M: EA; AEC Category: Q200; SizeArea_mm2: 1.28; SizeAreaWB_mm2: 4.68; SizeX_mm: 1.6; SizeY_mm: 0.8; SizeZ_mm: 1
signal-integrity model Cap
simulation model Cap
footprint 0603
footprint 0603M
footprint 0603L
footprint 0603_HV
footprint 0603S
pins: 1, 2

## GRM1885C1H332JA01D
designator C?  ValueDisplayed: 3300pF  (hidden comment: GRM1885C1H332JA01D)
CAP, CERM, 3300 pF, 50 V, +/- 5%, C0G/NP0, 0603; Manufacturer: MuRata; Polarized: N; CompType: Capacitor; Value: 3300pF; U/M: EA; Cap_F: 0.0000000033; Tolerance_%: 5; Value1: Unknown; VDC_V: 50; Value2: 50V; TaMin_C: -55; TaMax_C: 125; Cap_Case: 0603; SizeArea_mm2: 1.28; SizeAreaWB_mm2: 4.68; SizeX_mm: 1.6; SizeY_mm: 0.8; SizeZ_mm: 1; AEC Category: Q200
signal-integrity model Cap
simulation model Cap
footprint 0603
footprint 0603M
footprint 0603L
footprint 0603_HV
footprint 0603S
pins: 1, 2

## GRM1885C2A160JA01D
designator C?  ValueDisplayed: 16pF  (hidden comment: GRM1885C2A160JA01D)
CAP, CERM, 16 pF, 100 V, +/- 5%, C0G/NP0, 0603; Manufacturer: MuRata; Polarized: N; CompType: Capacitor; Value: 16pF; U/M: EA; Cap_F: 0.000000000016; Tolerance_%: 5; Value1: Unknown; VDC_V: 100; Value2: 100V; TaMin_C: -55; TaMax_C: 125; Cap_Case: 0603; SizeArea_mm2: 1.28; SizeAreaWB_mm2: 4.68; SizeX_mm: 1.6; SizeY_mm: 0.8; SizeZ_mm: 1; AEC Category: Q200
signal-integrity model Cap
simulation model Cap
footprint 0603
footprint 0603M
footprint 0603L
footprint 0603_HV
footprint 0603S
pins: 1, 2

## GRM1885C2A301JA01D
designator C?  ValueDisplayed: 300pF  (hidden comment: GRM1885C2A301JA01D)
CAP, CERM, 300pF, 100V, +/-5%, C0G/NP0, 0603; Manufacturer: MuRata; Cap_Case: 0603; Polarized: N; TaMax_C: 125; TaMin_C: -55; Tolerance_%: 5; VDC_V: 100; Cap_F: 0.0000000003; CompType: Capacitor; Value1: Unknown; U/M: EA
signal-integrity model Cap
simulation model Cap
footprint 0603
footprint 0603M
footprint 0603L
footprint 0603_HV
footprint 0603S
pins: 1, 2

## HTSW-103-09-G-S
designator J?
Header, 100mil, 3x1, Gold, TH; Manufacturer: Samtec; SymbolCreator: a0799628; Pitch_mm: 2.54; Gender: Male; Row_Count: 1; Cert_CSA: Y
footprint Samtec_HTSW-103-09-x-S
pins: 1, 2, 3
3 alternate drawings of the same symbol

## IEC_Caution
designator Logo?, comment CAUTION.  READ USER GUIDE BEFORE USE  (value not drawn)  (no BOM)
IEC 61010-1 Caution Warning; SymbolCreator: a0412235
footprint IEC_Caution_Medium
footprint IEC_Caution_Medium
footprint IEC_Caution_Small

## JMK212BJ226MG-T
designator C?  ValueDisplayed: 22µF  (hidden comment: JMK212BJ226MG-T)
CAP, CERM, 22 µF, 6.3 V, +/- 20%, X5R, 0805; Manufacturer: Taiyo Yuden; Polarized: N; CompType: Capacitor; Value: 22uF; U/M: EA; Cap_F: 0.000022; Tolerance_%: 20; Value1: Unknown; VDC_V: 6.3; Value2: 6.3V; TaMin_C: -55; TaMax_C: 85; Cap_Case: 0805; SizeArea_mm2: 2.5; SizeAreaWB_mm2: 6.75; SizeX_mm: 2; SizeY_mm: 1.25; SizeZ_mm: 1.45; AEC Category: Q200
signal-integrity model Cap
simulation model Cap
footprint 0805_HV
footprint 0805_HV1
footprint 0805
footprint 0805M
footprint 0805L
pins: 1, 2

## L101011MS02Q
designator S?  (value not drawn)
SWITCH SLIDE SPST 4A PCB, TH; Manufacturer: C&K Components; Symbol Creator: a0411947; VDC_V: 125; SwitchFunction: Off-On; PositionCount: 1; CurrentRating_mA: 4000
footprint SW_ L101011MS02Q
pins: 1, 2

## LFL182G45TC3B746
designator LF?  (value not drawn)
Filter for Communication Equipment, SMD; Manufacturer: MuRata; SymbolCreator: Altium; SizeAreaWB_mm2: 4.68; SizeArea_mm2: 1.28; SizeX_mm: 1.6; SizeY_mm: 0.8; SizeZ_mm: 0.7
footprint FIL_LFL18_TC1
pins: 1 IN, 2 GND, 3 OUT, 4 NC, 5 GND, 6 NC

## LLL185R71E103MA01L
designator C?  ValueDisplayed: 0.01µF  (hidden comment: LLL185R71E103MA01L)
CAP, CERM, 0.01 µF, 25 V, +/- 20%, X7R, 0306; Manufacturer: MuRata; Polarized: N; CompType: Capacitor; Value: 0.01uF; U/M: EA; Cap_F: 0.00000001; Tolerance_%: 20; Value1: Unknown; VDC_V: 25; Value2: 25V; TaMin_C: -55; TaMax_C: 125; Cap_Case: 0306; SizeArea_mm2: 1.28; SizeAreaWB_mm2: 4.68; SizeX_mm: 0.8; SizeY_mm: 1.6; SizeZ_mm: 0.6; AEC Category: Q200
signal-integrity model Cap
simulation model Cap
footprint 0306
pins: 1, 2

## LLL185R71H222MA01L
designator C?  ValueDisplayed: 2200pF  (hidden comment: LLL185R71H222MA01L)
CAP, CERM, 2200 pF, 50 V, +/- 20%, X7R, 0306; Manufacturer: MuRata; Polarized: N; CompType: Capacitor; Value: 2200pF; U/M: EA; Cap_F: 0.0000000022; Tolerance_%: 20; Value1: Unknown; VDC_V: 50; Value2: 50V; TaMin_C: -55; TaMax_C: 125; Cap_Case: 0306; SizeArea_mm2: 1.28; SizeAreaWB_mm2: 4.68; SizeX_mm: 0.8; SizeY_mm: 1.6; SizeZ_mm: 0.6; AEC Category: Q200
signal-integrity model Cap
simulation model Cap
footprint 0306
pins: 1, 2

## LM95233CISD
designator U?
Dual Remote Diode and Local Temperature Sensor with SMBus Interface and TruTherm Technology, 15-pin LLP; Manufacturer: Texas Instruments; PackageTopMarking: NS*UZXYTT*95233CI; PowerWise: Y; CompType: Temp Sensor IC
footprint SDA14B (SON, 14-Leads, Body 4x4mm, Pitch 0.5mm, NSC Recommended)
pins: 1 NC, 2 VDD (power), 3 NC, 4 NC, 5 D-, 6 D2+, 7 D1+, 8 GND (power), 9 A0 (in), 10 ~{TCRIT1} (oc), 11 ~{TCRIT2} (oc), 12 SMBDAT (io), 13 SMBCLK (in), 14 ~{TCRIT3} (oc), 15 DAP (power)

## LMC6762AIMX
designator U?
Dual Micro-Power Rail-to-Rail Input CMOS Comparator with Push-Pull Output, 8-pin Narrow SOIC; Manufacturer: Texas Instruments; PackageTopMarking: NSZXTT*LMC67*62AIM; PowerWise: N
footprint M08A_N (SOIC, 8-Leads, Body 4.9x3.9mm, Pitch 1.27mm, IPC Medium Density)
footprint M08A_L (SOIC, 8-Leads, Body 4.9x3.9mm, Pitch 1.27mm, IPC High Density)
footprint M08A_M (SOIC, 8-Leads, Body 4.9x3.9mm, Pitch 1.27mm, IPC Low Density)
pins on every part: 4 V- (power), 8 V+ (power)
part A pins: 1 OUTA (out), 2 INA- (in), 3 INA+ (in)
part B pins: 5 INB+ (in), 6 INB- (in), 7 OUTB (out)

## LMH5401IRMSR
designator U?
8GHz Ultra Wideband Fully Differential Amplifier, RMS0014A (UQFN-14); Alternate PartNumber: LMH5401IRMST; Manufacturer: Texas Instruments; SymbolCreator: Altium; SizeArea_mm2: 6.25; SizeAreaWB_mm2: 12.25; SizeX_mm: 2.5; SizeZ_mm: 0.6; CompType: IC; U/M: EA
footprint RMS0014A
pins: 1 VS+ (power) "Power supply pins, Positive Rail", 2 CM (in) "Output common-mode voltage control input pin", 3 VS- (power) "Power supply pins, Negative Rail", 4 FB+ (out) "No internal connection", 5 IN- (in) "Inverting input pin", 6 IN+ (in) "Noninverting input pin", 7 FB- (out) "No internal connection", 8 VS- (power), 9 PD (in) "Power down. High (>GND+1.2V) = low power (sleep) mode. Low (<GND +0.9V)= active.", 10 VS+ (power) "Power supply pins, Positive Rail", 11 GND (power) "Ground. This ground does not impact the signal path. This ground sets the lower logic level for the PD pin.", 12 OUT- (out) "Inverting output pin", 13 OUT+ (out) "Noninverting output pin", 14 GND (power) "Ground. This ground does not impact the signal path. This ground sets the lower logic level for the PD pin."
1 alternate drawing of the same symbol

## LMH6401IRMZR
designator U?
4.5 GHz Ultra Wideband Digital Variable Gain Amplifier, RMZ0016A (UQFN-HR-16); Alternate PartNumber: LMH6401IRMZT; Manufacturer: Texas Instruments; SymbolCreator: Altium; SizeArea_mm2: 9; SizeAreaWB_mm2: 16; SizeX_mm: 3; SizeZ_mm: 0.65; CompType: IC; U/M: EA
footprint RMZ0016A
pins: 1 SDI (in), 2 INP (in), 3 INM (in), 4 SDO (out), 5 VEE (power), 6 PD (in), 7 VOCM (in), 8 VCC (power), 9 GND (power), 10 OUTM (out), 11 OUTP (out), 12 GND (power), 13 VCC (power), 14 CLK (in), 15 ~{CS} (in), 16 VEE (power)
1 alternate drawing of the same symbol

## LMK61E2-SIAR
designator U?
Ultra-Low Jitter Programmable Oscillator with Internal EEPROM, SIA0008B; Alternate PartNumber: LMK61E2-SIAT; Manufacturer: Texas Instruments; SymbolCreator: Altium; CompType: IC; U/M: EA
footprint SIA0008B
pins: 1 OE (in), 2 ADD (in), 3 GND (power), 4 OUTP (out), 5 OUTN (out), 6 VDD (power), 7 SDA (io), 8 SCL (in)

## LMK00304SQ/NOPB
designator U?
3.1-GHz Differential Clock Buffer/Level Translator, RTV0032A (WQFN-32); Manufacturer: Texas Instruments; SymbolCreator: a0411947; SizeArea_mm2: 25; SizeAreaWB_mm2: 49; SizeX_mm: 5; SizeZ_mm: 0.8; CompType: IC; U/M: EA
footprint RTV0032A
pins: 1 GND (power), 2 VccoA (power), 3 CLKoutA0 (out), 4 ~{CLKoutA0} (out), 5 VccoA (power), 6 CLKoutA1 (out), 7 ~{CLKoutA1} (out), 8 GND (power), 9 CLKout_TYPE0 (in), 10 Vcc (power), 11 OSCin (in), 12 OSCout (out), 13 CLKin_SEL0 (in), 14 CLKin0 (in), 15 ~{CLKin0} (in), 16 CLKin_SEL1 (in), 17 GND (power), 18 ~{CLKoutB1} (out), 19 CLKoutB1 (out), 20 VccoB (power), 21 ~{CLKoutB0} (out), 22 CLKoutB0 (out), 23 VccoB (power), 24 GND (power), 25 NC, 26 ~{CLKin1} (in), 27 CLKin1 (in), 28 Vcc (power), 29 REFout (out), 30 VccoC (power), 31 REFout_EN (in), 32 CLKout_TYPE1 (in), 33 DAP (power)
1 alternate drawing of the same symbol

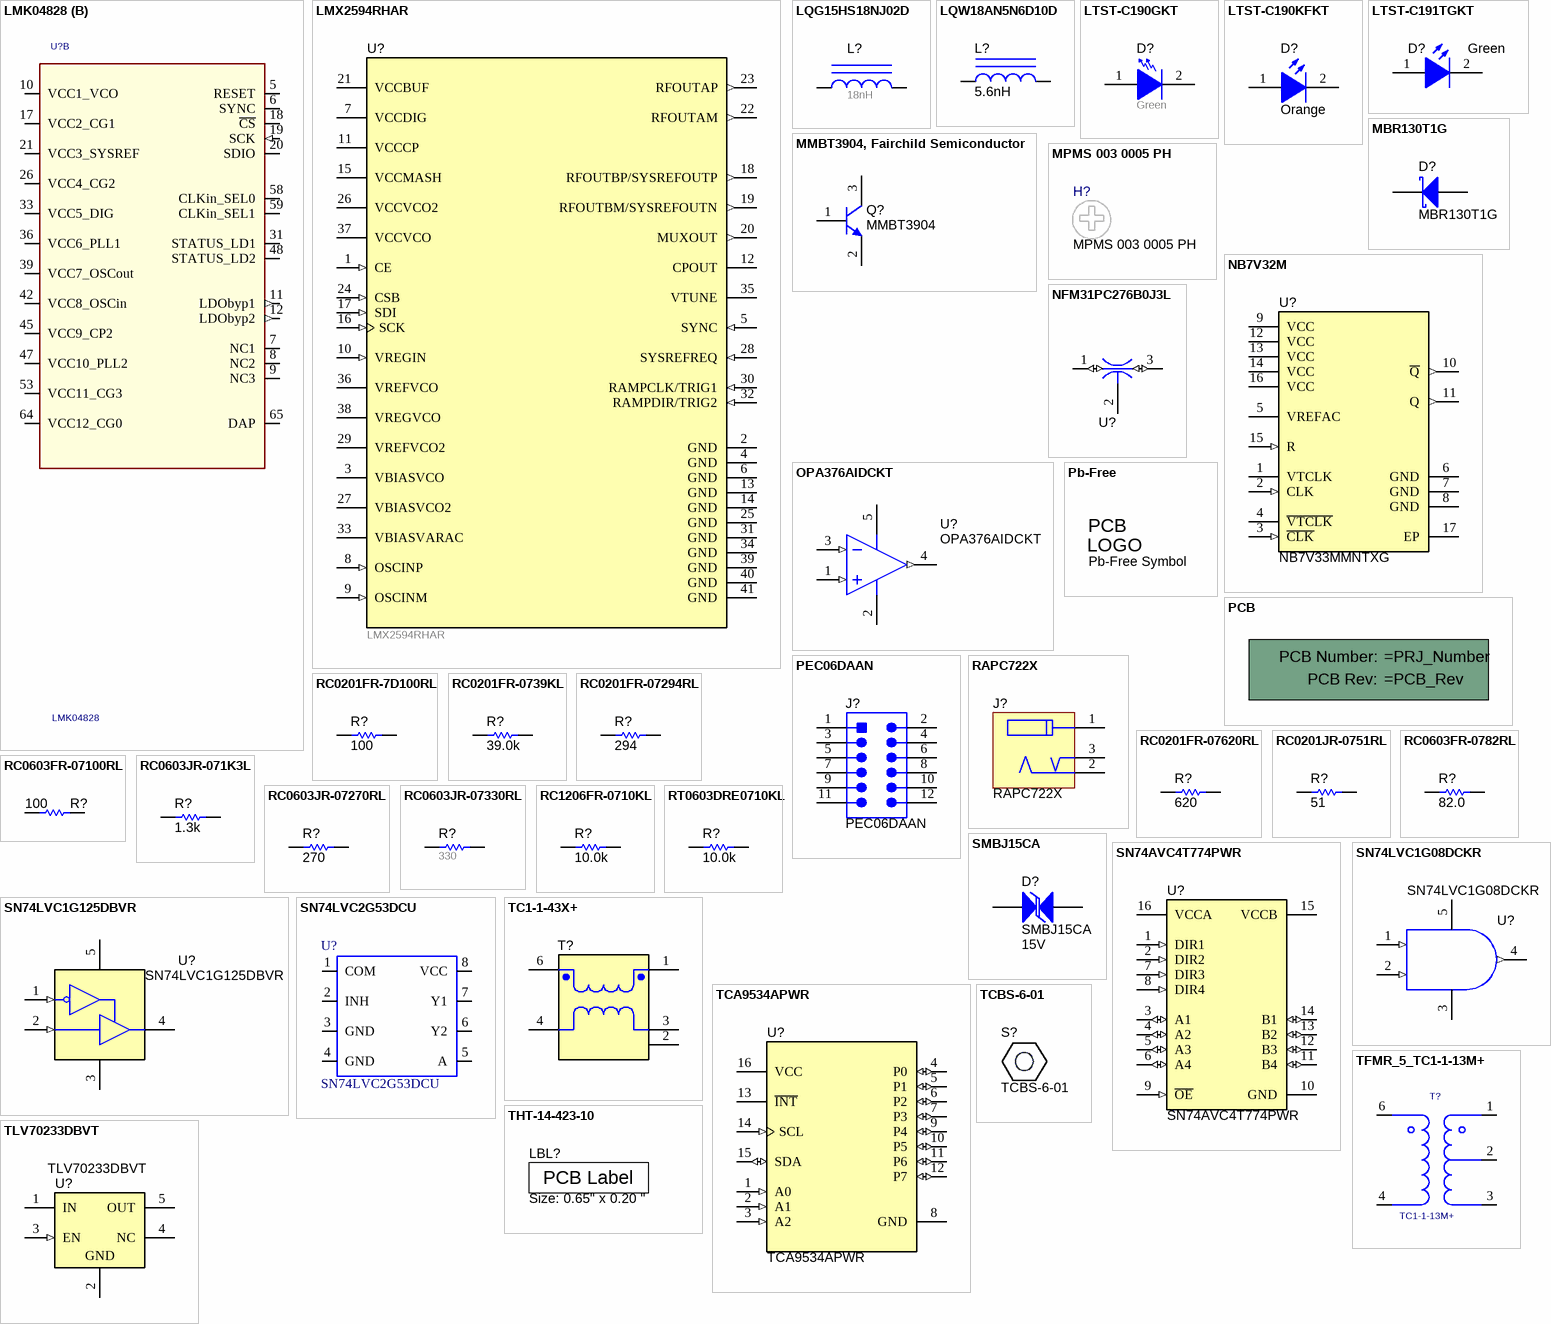
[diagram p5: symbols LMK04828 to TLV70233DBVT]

## LMK04828
designator U?
LMK04828BISQE/NOPB; Manufacturer: Texas Instruments
footprint NKD0064A (QFN, 64-Leads, Body 9x9mm, Pitch 0.5mm)
part A pins: 1 DCLKOUT0p (out), 2 DCLKOUT0n (out), 3 SDCLKOUT1p (out), 4 SDCLKOUT1n (out), 13 SDCLKOUT3p (out), 14 SDCLKOUT3n (out), 15 DCLKOUT2p (out), 16 DCLKOUT2n (out), 22 SDCLKOUT5p (out), 23 SDCLKOUT5n (out), 24 DCLKOUT4p (out), 25 DCLKOUT4n (out), 27 DCLKOUT6p (out), 28 DCLKOUT6n (out), 29 SDCLKOUT7p (out), 30 SDCLKOUT7n (out), 32 CPOUT1 (out), 34 CLKIN1p/FBCLKINp/FINp (in), 35 CLKIN1n/FBCLKINn/FINn (in), 37 CLKIN0p (in), 38 CLKIN0n (in), 40 OSCOUTp (out), 41 OSCOUTn (out), 43 OSCINp (in), 44 OSCINn (in), 46 CPOUT2 (out), 49 SDCLKOUT9p (out), 50 SDCLKOUT9n (out), 51 DCLKOUT8p (out), 52 DCLKOUT8n (out), 54 DCLKOUT10p (out), 55 DCLKOUT10n (out), 56 SDCLKOUT11p (out), 57 SDCLKOUT11n (out), 60 SDCLKOUT13p (out), 61 SDCLKOUT13n (out), 62 DCLKOUT12p (out), 63 DCLKOUT12n (out)
part B pins: 5 RESET (io), 6 SYNC (io), 7 NC1, 8 NC2, 9 NC3, 10 VCC1_VCO (power), 11 LDObyp1 (out), 12 LDObyp2 (out), 17 VCC2_CG1 (power), 18 ~{CS} (io), 19 SCK (in), 20 SDIO (io), 21 VCC3_SYSREF (power), 26 VCC4_CG2 (power), 31 STATUS_LD1 (io), 33 VCC5_DIG (power), 36 VCC6_PLL1 (power), 39 VCC7_OSCout (power), 42 VCC8_OSCin (power), 45 VCC9_CP2 (power), 47 VCC10_PLL2 (power), 48 STATUS_LD2 (io), 53 VCC11_CG3 (power), 58 CLKin_SEL0 (io), 59 CLKin_SEL1 (io), 64 VCC12_CG0 (power), 65 DAP (power)

## LMX2594RHAR
designator U?
High Performance, Wideband PLLatinum RF Synthesizer, RHA0040A (VQFN-40); Alternate PartNumber: LMX2594RHAT; Manufacturer: Texas Instruments; SymbolCreator: Altium; SizeArea_mm2: 36; SizeAreaWB_mm2: 64; SizeX_mm: 6; SizeZ_mm: 1; CompType: IC; U/M: EA
footprint RHA0040A (QFN, 40-Leads, Body 6x6mm, Pitch 0.5mm, Thermal Pad 4.6x4.6mm, TI Recommended)
footprint RHA0040A_NV
footprint RHA0040C
pins: 1 CE (in), 2 GND (power), 3 VBIASVCO, 4 GND (power), 5 SYNC (in), 6 GND (power), 7 VCCDIG (power), 8 OSCINP (in), 9 OSCINM (in), 10 VREGIN (in), 11 VCCCP (power), 12 CPOUT, 13 GND (power), 14 GND (power), 15 VCCMASH (power), 16 SCK (in), 17 SDI (in), 18 RFOUTBP/SYSREFOUTP (out), 19 RFOUTBM/SYSREFOUTN (out), 20 MUXOUT (out), 21 VCCBUF (power), 22 RFOUTAM (out), 23 RFOUTAP (out), 24 CSB (in), 25 GND (power), 26 VCCVCO2 (power), 27 VBIASVCO2, 28 SYSREFREQ (in), 29 VREFVCO2, 30 RAMPCLK/TRIG1 (in), 31 GND (power), 32 RAMPDIR/TRIG2 (in), 33 VBIASVARAC, 34 GND (power), 35 VTUNE, 36 VREFVCO, 37 VCCVCO (power), 38 VREGVCO, 39 GND (power), 40 GND (power), 41 GND (power)

## LQG15HS18NJ02D
designator L?  ValueDisplayed: 18nH  (hidden comment: LQG15HS18NJ02D)
Inductor, Multilayer, Air Core, 18 nH, 0.3 A, 0.36 ohm, SMD; Manufacturer: MuRata; Value: 18nH; Ind_H: 18.0E-9; Imax_A: 0.3; Irms: 0.3A @ C rise; Isat: 0.3A @ % inductance drop; DCR_ohm: 0.36; Value2: 0.3A; AEC Category: Q200
signal-integrity model Inductor
simulation model Inductor
footprint IND_LQG15H
pins: 1, 2

## LQW18AN5N6D10D
designator L?  ValueDisplayed: 5.6nH  (hidden comment: LQW18AN5N6D10D)
Inductor, Wirewound, 5.6 nH, 0.9 A, 0.045 ohm, SMD; Manufacturer: MuRata; Value: 5.6nH; Ind_H: 5.6E-9; Imax_A: 0.9; Irms: 0.9A @ C rise; DCR_ohm: 0.045; Value2: 0.9A; SizeAreaWB_mm2: 4.68; SizeArea_mm2: 1.28; SizeX_mm: 1.6; SizeY_mm: 0.8; SizeZ_mm: 1; AEC Category: Q200; AEC Qualified: N
signal-integrity model Inductor
simulation model Inductor
footprint LQW18A
pins: 1, 2

## LTST-C190GKT
designator D?  value Green  (hidden comment: LTST-C190GKT)
LED, Green, SMD; Manufacturer: Lite-On; Vf_V: 2.1; Value2: 2.1V; Io_A: 0.02; Power_TotalModule: 0.1; Value1: 0.1W; U/M: EA
signal-integrity model Diode
footprint LED_LTST-C190
pins: 1 A, 2 K

## LTST-C190KFKT
designator D?  value Orange  (hidden comment: LTST-C190KFKT)
LED, Orange, SMD; Manufacturer: Lite-On; Type: AlInGaP; Vf_V: 2; Value2: 2V; Io_A: 0.02; Power_TotalModule: 0.075; Value1: 0.075W; U/M: EA
signal-integrity model Diode
footprint LED_LTST-C190
pins: 1 A, 2 K

## LTST-C191TGKT
designator D?  value Green  (hidden comment: LTST-C191TGKT)
LED, Green, SMD; Manufacturer: Lite-On; Type: InGaN; Vf_V: 3.2; Value2: 3.2V; Io_A: 0.02; Value1: W; U/M: EA
signal-integrity model Diode
footprint LTST-C191_Green
pins: 1 A, 2 K

## MBR130T1G
designator D?
Diode, Schottky, 30 V, 1 A, SOD-123; Manufacturer: ON Semiconductor; U/M: EA; Vf_V: 0.47; Value: 30V; Value1: 1A; Value2: 0.47V; Io_A: 1; Vr_V: 30; TJmax_C: 125; RJC_CperW: 108; SizeAreaWB_mm2: 13.095; SizeArea_mm2: 6.545; SizeX_mm: 3.85; SizeY_mm: 1.7; SizeZ_mm: 1.35; AEC Category: Q101
signal-integrity model Diode
simulation model mbr130prl
footprint SOD-123
pins: 1 K, 2 A

## MMBT3904, Fairchild Semiconductor
designator Q?, comment MMBT3904
Transistor, NPN, 40 V, 0.2 A, SOT-23; Manufacturer: Fairchild Semiconductor; CompType: BJT; PNP: 0; NPN: 1; Vceo_V: 40; Vcesat1_V: 0.2; Value: 40 V; Value1: 0.2 A; HfeMax: 300; TaMin_C: -55; TaMax_C: 150; SizeAreaWB_mm2: 14; SizeArea_mm2: 7.5; SizeX_mm: 2.5; SizeY_mm: 3; SizeZ_mm: 1.1; U/M: EA; AEC Category: Q101
footprint SOT-23
footprint SOT-23M
footprint SOT-23L
simulation model MMBT3904
pins: 1 B, 2 E, 3 C

## MPMS 003 0005 PH
designator H?  (mechanical)
MACHINE SCREW PAN PHILLIPS M3 5mm; Manufacturer: B&F Fastener Supply; CompType: Hardware
footprint BuildingFastener_MPMS_003_0005_PH

## NB7V32M
designator U?, comment NB7V33MMNTXG
1.8V / 2.5V, 10GHz ÷4 Clock Divider with CML Outputs, QFN-16; Manufacturer: ON Semiconductor
footprint QFN16-3x3MM_0_5 (QFN, 16-Leads, Body 3x3mm, Pitch 0.5mm)
pins: 1 VTCLK, 2 CLK (in), 3 ~{CLK} (in), 4 ~{VTCLK}, 5 VREFAC (power), 6 GND (power), 7 GND (power), 8 GND (power), 9 VCC (power), 10 ~{Q} (out), 11 Q (out), 12 VCC (power), 13 VCC (power), 14 VCC (power), 15 R (in), 16 VCC (power), 17 EP (power)

## NFM31PC276B0J3L
designator U?  (value not drawn)
FILTER LC HIGH FREQ 27uF 1206; Manufacturer: MuRata; SymbolCreator: Altium
footprint Murata_NFM31P
pins: 1 (io), 2 (power), 3 (io)

## OPA376AIDCKT
designator U?
Precision, Low Noise, Low Iq Operational Amplifier, 2.2 to 5.5 V, -40 to 125 degC, 5-pin SOT23 (DCK0005A), Green (RoHS & no Sb/Br); Manufacturer: Texas Instruments; Alternate PartNumber: Equivalent; CMRR(Min)(dB): 76; IIB(Max)(pA): 10; Iq per channel(Max)(mA): 0.95; Number of Channels: 1; Offset Drift(Typ)(uV/C): 0.32; Slew Rate(Typ)(V/us): 2; Sub Family: Low Input Bias Current Amp (<=10pA), Low Noise Amp (<=10nV/rtHz), Low Offset Voltage Amplifier (<=500uV), Low Supply Voltage Amplifier (<=2.7V), Precision Amplifier; Total Supply Voltage(Max)(+5V is 5, +/-5V is 10): 5.5; Total Supply Voltage(Min)(+5V is 5, +/-5V is 10): 2.2; Vio (25C)(Max)(mV): 0.025; Vn at 1kHz(Typ)(nV/rtHz): 7.5
footprint DCK0005A_N (SOT23, 5-Leads, Body 2x1.25mm, Pitch 0.65mm, IPC High Density)
footprint DCK0005A_L (SOT23, 5-Leads, Body 2x1.25mm, Pitch 0.65mm, IPC High Density)
footprint DCK0005A_M (SOT23, 5-Leads, Body 2x1.25mm, Pitch 0.65mm, IPC Low Density)
pins: 1 IN+ (in), 2 V- (power), 3 IN- (in), 4 OUT (out), 5 V+ (power)

## Pb-Free
designator Logo?, comment Pb-Free Symbol  (no BOM)
SymbolCreator: a0412235
footprint Pb-Free_Overlay_Medium
footprint Pb-Free_Overlay_Small

## PCB
designator !PCB?, comment Printed Circuit Board  (value not drawn)  (mechanical)
Manufacturer: Any; SymbolCreator: a0412235; CompType: PCB
1 alternate drawing of the same symbol

## PEC06DAAN
designator J?
Header, 100mil, 6x2, Tin, TH; Manufacturer: Sullins Connector Solutions; SymbolCreator: a0412235; Pitch_mm: 2.54; Gender: Male; Shrouded: N; Row_Count: 2; Current_A: 3; Voltage_V: 1800; Cert_UL: Y; Green_Lifecycle: Not Set; Green_REACh: Incomplete
footprint CONN_PEC06DAAN
pins: 1, 2, 3, 4, 5, 6, 7, 8, 9, 10, 11, 12
1 alternate drawing of the same symbol

## RAPC722X
designator J?
Power Jack, mini, 2.1mm OD, R/A, TH; Manufacturer: Switchcraft; SymbolCreator: a0799628
footprint CONN_RAPC722X
pins: 1, 2, 3

## RC0201FR-7D100RL
designator R?  ValueDisplayed: 100  (hidden comment: RC0201FR-7D100RL)
RES, 100, 1%, 0.05 W, 0201; Manufacturer: Yageo America; CompType: Resistor; Value: 100; Value_Code: 100R; Tolerance_%: 1; Power_W: 0.05; Value2: 0.05W; VDC_V: 25; TempCo: 200 ppm/C; SizeArea_mm2: 0.18; SizeX_mm: 0.6; SizeY_mm: 0.3; SizeZ_mm: 0.26; EIA_Code: E96; U/M: EA; AEC Category: Q200; AEC Qualified: N
signal-integrity model Resistor
simulation model Resistor
footprint 0201
footprint 0201M
footprint 0201L
footprint 0201_Silk
pins: 1, 2

## RC0201FR-0739KL
designator R?  ValueDisplayed: 39.0k  (hidden comment: RC0201FR-0739KL)
RES, 39.0 k, 1%, 0.05 W, 0201; Manufacturer: Yageo America; CompType: Resistor; Value: 39.0k; Res_ohm: 39000; Value_Code: 39k0; Tolerance_%: 1; Power_W: 0.05; Value2: 0.05W; VDC_V: 25; TempCo: 200 ppm/C; SizeArea_mm2: 0.18; SizeX_mm: 0.6; SizeY_mm: 0.3; SizeZ_mm: 0.26; U/M: EA; AEC Category: Q200; AEC Qualified: N
signal-integrity model Resistor
simulation model Resistor
footprint 0201
footprint 0201M
footprint 0201L
footprint 0201_Silk
pins: 1, 2

## RC0201FR-07294RL
designator R?  ValueDisplayed: 294  (hidden comment: RC0201FR-07294RL)
RES, 294, 1%, 0.05 W, 0201; Manufacturer: Yageo America; CompType: Resistor; Value: 294; Value_Code: 294R; Tolerance_%: 1; Power_W: 0.05; Value2: 0.05W; VDC_V: 25; TempCo: 200 ppm/C; SizeArea_mm2: 0.18; SizeX_mm: 0.6; SizeY_mm: 0.3; SizeZ_mm: 0.26; EIA_Code: E96; U/M: EA; AEC Category: Q200; AEC Qualified: N
signal-integrity model Resistor
simulation model Resistor
footprint 0201_adc (Data from Kemet datasheet CC101_COM dated 7/28/11)
footprint 0201M
footprint 0201L
footprint 0201_Silk
pins: 1, 2

## RC0201FR-07620RL
designator R?  ValueDisplayed: 620  (hidden comment: RC0201FR-07620RL)
RES, 620, 1%, 0.05 W, 0201; Manufacturer: Yageo America; CompType: Resistor; Value: 620; Value_Code: 620R; Tolerance_%: 1; Power_W: 0.05; Value2: 0.05W; VDC_V: 25; TempCo: 200 ppm/C; SizeArea_mm2: 0.18; SizeX_mm: 0.6; SizeY_mm: 0.3; SizeZ_mm: 0.26; U/M: EA; AEC Category: Q200; AEC Qualified: N
signal-integrity model Resistor
simulation model Resistor
footprint 0201
footprint 0201M
footprint 0201L
footprint 0201_Silk
pins: 1, 2

## RC0201JR-0751RL
designator R?  ValueDisplayed: 51  (hidden comment: RC0201JR-0751RL)
RES, 51, 5%, 0.05 W, 0201; Manufacturer: Yageo America; CompType: Resistor; Value: 51; Value_Code: 51R0; Tolerance_%: 5; Power_W: 0.05; Value2: 0.05W; VDC_V: 25; TempCo: 200 ppm/C; SizeArea_mm2: 0.18; SizeX_mm: 0.6; SizeY_mm: 0.3; SizeZ_mm: 0.26; EIA_Code: E24; U/M: EA; AEC Category: Q200; AEC Qualified: N
signal-integrity model Resistor
simulation model Resistor
footprint 0201
footprint 0201M
footprint 0201L
footprint 0201_Silk
pins: 1, 2

## RC0603FR-0782RL
designator R?  ValueDisplayed: 82.0  (hidden comment: RC0603FR-0782RL)
RES, 82.0, 1%, 0.1 W, 0603; Manufacturer: Yageo America; CompType: Resistor; Value: 82.0; Res_ohm: 82; Value_Code: 82R0; Tolerance_%: 1; Power_W: 0.1; Value2: 0.1W; VDC_V: 150; TempCo: 200 ppm/C; SizeArea_mm2: 1.28; SizeX_mm: 1.6; SizeY_mm: 0.8; U/M: EA; AEC Category: Q200
signal-integrity model Resistor
simulation model Resistor
footprint 0603
footprint 0603M
footprint 0603L
footprint 0603_HV
footprint 0603S
pins: 1, 2

## RC0603FR-07100RL
designator R?  ValueDisplayed: 100  (hidden comment: RC0603FR-07100RL)
RES, 100, 1%, 0.1 W, 0603; Manufacturer: Yageo America; CompType: Resistor; Value: 100; Value_Code: 100R; Tolerance_%: 1; Power_W: 0.1; Value2: 0.1W; VDC_V: 150; TempCo: 200 ppm/C; SizeArea_mm2: 1.28; SizeX_mm: 1.6; SizeY_mm: 0.8; EIA_Code: E96; U/M: EA; AEC Category: Q200
signal-integrity model Resistor
simulation model Resistor
footprint 0603
footprint 0603M
footprint 0603L
footprint 0603_HV
footprint 0603S
pins: 1, 2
